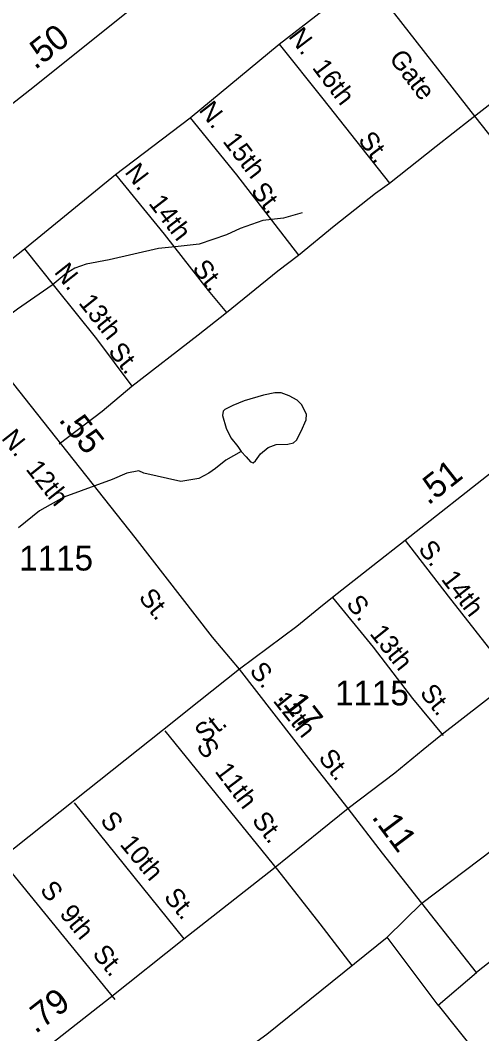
# Model space of a CAD drawing. Extents: x 2056842 to 2160602, y 826753 to 1016856.
# Drawn here: x 2067778 to 2070103, y 864781 to 869878 of the extents above; entities that cross this region are included whole.
import ezdxf

# ---------------------------------------------------------------- set-up
doc = ezdxf.new("R2010")
doc.units = 0
for name, color, linetype in [('Exist Hydrographic Creek Single Shore', 7, 'Continuous'), ('Exist Hydrographic Misc Water Feature', 7, 'Continuous'), ('Exist Road Non-System Type 51', 7, 'Continuous'), ('Exist Road Non-System Type 51 Label', 7, 'Continuous'), ('Exist Road Secondary Mileage Hundredths English Label', 7, 'Continuous'), ('Exist Road Secondary Type 51 Attributed', 7, 'Continuous'), ('Exist Road Secondary Type 51 Label', 7, 'Continuous'), ('Exist Road Secondary Type 51 Number Label', 7, 'Continuous')]:
    doc.layers.add(name, color=color, linetype=linetype)

msp = doc.modelspace()

# ---------------------------------------------------------------- linework, layer by layer
at = {"layer": 'Exist Hydrographic Creek Single Shore'}
for points in [[(2069198.2, 868909.3), (2069104.7, 868883), (2069000.5, 868870.8), (2068886.7, 868830.4), (2068816.4, 868798.5), (2068678.8, 868752.4), (2068558.6, 868738.1), (2068474.8, 868729.8), (2068227.1, 868673.6), (2068111.2, 868651.1), (2068053, 868631.1), (2068009.1, 868604.8), (2067939.2, 868544.9), (2067765.3, 868424.7), (2067609.5, 868310.4), (2067545.7, 868254.3)], [(2068891.6, 867709.5), (2068814.3, 867665.1), (2068761.1, 867623.3), (2068728.2, 867599.3), (2068677.6, 867572.6), (2068587.7, 867558.7), (2068401.7, 867600.5), (2068376.4, 867611.9), (2068315.6, 867600.5), (2068240.9, 867568.8), (2067997.8, 867478.9), (2067874.9, 867410.5), (2067769.9, 867324.3)]]:
    msp.add_lwpolyline(points, dxfattribs=at)
at = {"layer": 'Exist Hydrographic Misc Water Feature'}
msp.add_lwpolyline([(2068891.6, 867709.5), (2068915.6, 867682.9), (2068938.4, 867656.3), (2068952.3, 867652.5), (2068962.5, 867662.6), (2068989.1, 867698.1), (2069027, 867729.7), (2069067.6, 867745), (2069125.8, 867746.2), (2069154.9, 867752.6), (2069170.1, 867765.2), (2069192.9, 867810.8), (2069218.2, 867869.1), (2069220.8, 867897), (2069194.2, 867945.1), (2069173.9, 867966.7), (2069132.1, 867988.2), (2069092.9, 868003.4), (2069061.2, 868003.4), (2069004.2, 867992), (2068906.8, 867964.1), (2068848.5, 867940.1), (2068808, 867921.1), (2068800.4, 867912.2), (2068797.9, 867889.4), (2068815.6, 867826), (2068838.4, 867777.9), (2068873.8, 867734.8), (2068891.6, 867709.5)], dxfattribs=at)
at = {"layer": 'Exist Road Non-System Type 51'}
for p, q in [((2068634.7, 869386.8), (2069083.1, 869757.9)), ((2068257.9, 869102.1), (2068634.7, 869386.8)), ((2067799.8, 868728.7), (2068257.9, 869102.1)), ((2067436.4, 868444), (2067799.8, 868728.7)), ((2068507.3, 866303.9), (2069073.8, 865605)), ((2068049.9, 865942.7), (2068602.8, 865257.6)), ((2070958, 865788), (2070076.3, 865088.1)), ((2067679.3, 865659), (2068254.4, 864952.4)), ((2070076.3, 865088.1), (2069800.3, 865437.4)), ((2069882.6, 864924.1), (2069626.8, 865266.7)), ((2069882.6, 864924.1), (2070076.3, 865088.1))]:
    msp.add_line(p, q, dxfattribs=at)
for points in [[(2069083.1, 869757.9), (2069651.4, 870198.4), (2069936.6, 870427.2)], [(2069083.1, 869757.9), (2069302.1, 869482.2), (2069638.7, 869058.8)], [(2070044.1, 869378.5), (2070233.8, 869526.1), (2070485.6, 869724.4)], [(2068634.7, 869386.8), (2068867.1, 869100.6), (2069179.2, 868695.9)], [(2069638.7, 869058.8), (2069872.6, 869245.2), (2070044.1, 869378.5)], [(2068257.9, 869102.1), (2068503.7, 868802.4), (2068724.1, 868519.2), (2068816.5, 868408.9)], [(2069179.2, 868695.9), (2069359.4, 868843.4), (2069567.2, 869008.2), (2069638.7, 869058.8)], [(2067799.8, 868728.7), (2067957, 868529.7), (2068162.5, 868276.3), (2068340.5, 868037)], [(2068816.5, 868408.9), (2069076.4, 868616.9), (2069179.2, 868695.9)], [(2068340.5, 868037), (2068675, 868295.6), (2068816.5, 868408.9)], [(2067974.8, 867747.1), (2068191.6, 867911.8), (2068340.5, 868037)], [(2069717.7, 867261.2), (2069933.3, 866982), (2070134.4, 866725.7), (2070275.5, 866558.3)], [(2069350.5, 866974.2), (2069555.3, 866725.3), (2069753.4, 866467.4), (2069908.7, 866280)], [(2069073.8, 865605), (2069287.2, 865333.2), (2069449.2, 865123.3)], [(2069882.6, 864924.1), (2070088.2, 864667.7), (2070630.4, 865079.1), (2071294.8, 865611.4)]]:
    msp.add_lwpolyline(points, dxfattribs=at)
at = {"layer": 'Exist Road Secondary Type 51 Attributed'}
for p, q in [((2070181.7, 867627.1), (2069717.7, 867261.2)), ((2070267.1, 866569), (2069896.1, 866280.7))]:
    msp.add_line(p, q, dxfattribs=at)
for points in [[(2069141.2, 870568.8), (2068835.8, 870324.4), (2068386.7, 869973.3), (2067826.6, 869526.1), (2067231.5, 869060.3), (2067062.8, 868908.5)], [(2069141.2, 870568.8), (2069519.3, 870096), (2070065.6, 869395.3), (2070976, 868248.9)], [(2068882.3, 866613.9), (2068747.2, 866776), (2068357.7, 867276.1), (2067062.8, 868908.5)], [(2069717.7, 867261.2), (2069554.6, 867133.7), (2069350.5, 866974.2)], [(2069350.5, 866974.2), (2069282, 866919.1), (2069171, 866828.9), (2068882.3, 866613.9)], [(2069800.3, 865437.4), (2070743.3, 866148.4), (2070985.3, 866342.9), (2071468, 866748.4), (2071672.6, 866905.6)], [(2068882.3, 866613.9), (2068677.1, 866451.8), (2068494.3, 866306.1), (2068053, 865954.9), (2067673.8, 865654.7), (2067195.8, 865281.9), (2066793.8, 864958.7), (2066395.6, 864631.8), (2065774.9, 864160.6)], [(2069429.8, 865913.2), (2069243.2, 866150.6), (2068882.3, 866613.9)], [(2069896.1, 866280.7), (2069808.3, 866207.9), (2069664.2, 866091.9), (2069429.8, 865913.2)], [(2069429.8, 865913.2), (2069291, 865800.4), (2069053.2, 865610.1), (2068602.8, 865256.1), (2068231.2, 864961.7), (2067771.9, 864600.3), (2067596.5, 864460.5), (2067389.9, 864292.4), (2066924.6, 863928.1), (2066573.8, 863652.9), (2066328.5, 863461.1), (2066307.2, 863441.6), (2066291.5, 863420.8), (2066292.2, 863396.5), (2066310.8, 863366.4), (2066374.5, 863286.9)], [(2069800.3, 865437.4), (2069602.2, 865689.3), (2069429.8, 865913.2)], [(2064684.1, 855839.6), (2064643.1, 855944), (2064589.1, 856124.9), (2064578.7, 856311.9), (2064608.8, 856568.6), (2064801, 857754.3), (2065030.5, 859012.8), (2065226.7, 860248.4), (2065364.9, 861035.1), (2065425.1, 861317.8), (2065553.9, 861629.5), (2065725.2, 861986), (2065930.8, 862276.9), (2066130.2, 862526.4), (2066317.1, 862696.8), (2066825, 863107.3), (2067775.2, 863846.1), (2068132.4, 864147.5), (2068556.1, 864440.6), (2069020.3, 864778.3), (2069626.8, 865266.7), (2069800.3, 865437.4)]]:
    msp.add_lwpolyline(points, dxfattribs=at)

# ---------------------------------------------------------------- texts
at = {"layer": 'Exist Road Non-System Type 51 Label'}
for s, rotation, p in [('N.  16th', 307.2946, (2069125.7, 869796.2)), ('N.  15th', 307.5565, (2068674.4, 869425.3)), ('St.', 307.2612, (2069476.3, 869274.4)), ('N.  14th', 307.3913, (2068301.4, 869113.8)), ('St.', 307.8565, (2068936.1, 869017.8)), ('N.  13th', 308.4809, (2067945.8, 868610.3)), ('St.', 308.4286, (2068641.1, 868628.1)), ('St.', 308.5837, (2068217.4, 868211.2)), ('S.  14th', 307.3913, (2069779.2, 867217.7)), ('S.  13th', 308.4809, (2069416.1, 866941.4)), ('S.  12th', 308.4138, (2068929.3, 866604.4)), ('St.', 308.4809, (2069787, 866493.4)), ('S  11th', 307.0667, (2068661.6, 866224.2)), ('St.', 308.4138, (2069276.3, 866166.8)), ('S  10th', 309.765, (2068177.1, 865851.1)), ('St.', 307.0667, (2068941.5, 865853.6)), ('S  9th', 309.3838, (2067873.9, 865502.1)), ('St.', 309.765, (2068497.6, 865465.9)), ('St.', 309.3838, (2068137.8, 865180.6))]:
    msp.add_text(s, height=95, rotation=rotation, dxfattribs=at).set_placement(p)
at = {"layer": 'Exist Road Secondary Mileage Hundredths English Label'}
for s, rotation, p in [('.50', 38.2209, (2067853.7, 869626)), ('.55', 308.4222, (2067968.3, 867867.5)), ('.51', 38.2613, (2069833.2, 867435.8)), ('.17', 307.9251, (2069069.9, 866474.8)), ('.11', 306.8698, (2069545, 865869.7)), ('.79', 37.9498, (2067855.8, 864777.6))]:
    msp.add_text(s, height=125, rotation=rotation, dxfattribs=at).set_placement(p)
at = {"layer": 'Exist Road Secondary Type 51 Label'}
for s, rotation, p in [('Gate', 307.5531, (2069632.2, 869685.1)), ('N.  12th', 308.4138, (2067680.1, 867774.3)), ('St.', 308.4138, (2068371, 866974)), ('St.', 37.6598, (2068704, 866238.4))]:
    msp.add_text(s, height=95, rotation=rotation, dxfattribs=at).set_placement(p)
at = {"layer": 'Exist Road Secondary Type 51 Number Label'}
for p in [(2067773.2, 867110.4), (2069363.7, 866431.8)]:
    msp.add_text('1115', height=125, dxfattribs=at).set_placement(p)

doc.saveas('drawing.dxf')
